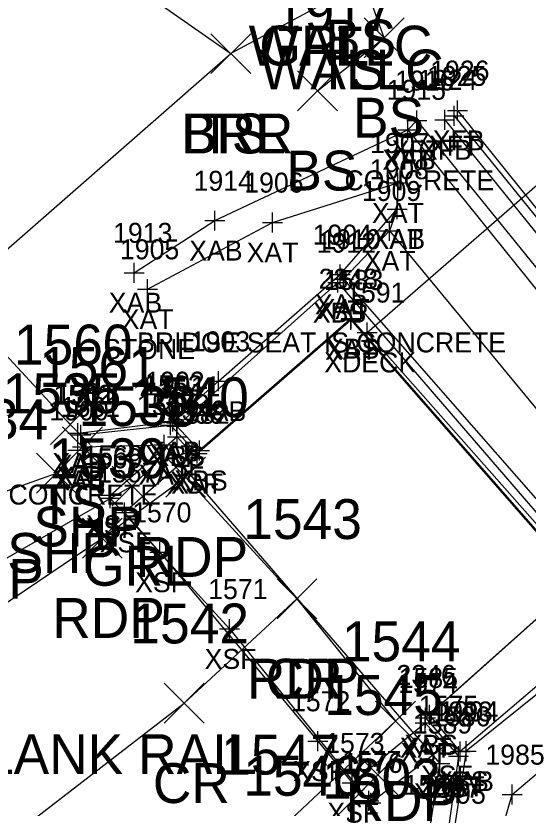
# Model space of a CAD drawing. Extents: x 1647133 to 1649138, y 411736 to 414924.
# Drawn here: x 1648828.16 to 1648853.85, y 412085.76 to 412125.47 of the extents above; entities that cross this region are included whole.
import ezdxf

# ---------------------------------------------------------------- set-up
doc = ezdxf.new("R2010")
doc.units = 0
for name, color, linetype in [('B_A', 7, 'Continuous'), ('B_C', 7, 'Continuous'), ('B_I', 7, 'Continuous'), ('B_TIC', 7, 'Continuous'), ('BDEFAULT', 7, 'Continuous'), ('BELB', 7, 'Continuous'), ('BFT', 7, 'Continuous'), ('BSE', 7, 'Continuous'), ('BSUBM', 7, 'Continuous'), ('L_A', 7, 'Continuous'), ('L_I', 7, 'Continuous'), ('L_TIC', 7, 'Continuous'), ('LABL', 7, 'Continuous'), ('LELB', 7, 'Continuous'), ('P_A', 7, 'Continuous'), ('P_I', 7, 'Continuous'), ('P_TIC', 7, 'Continuous'), ('PET', 7, 'Continuous'), ('PRC', 7, 'Continuous'), ('PSP', 7, 'Continuous'), ('R_A', 7, 'Continuous'), ('R_C', 7, 'Continuous'), ('R_I', 7, 'Continuous'), ('R_TIC', 7, 'Continuous'), ('RGR', 7, 'Continuous'), ('U_I', 7, 'Continuous')]:
    doc.layers.add(name, color=color, linetype=linetype)

msp = doc.modelspace()

# ---------------------------------------------------------------- linework, layer by layer
at = {"layer": 'B_TIC'}
for p, q in [((1648850.313, 412120.73), (1648850.388, 412120.73)), ((1648848.266, 412120.228), (1648848.341, 412120.228)), ((1648849.667, 412120.263), (1648849.743, 412120.263)), ((1648850.135, 412120.462), (1648850.211, 412120.462)), ((1648847.822, 412119.764), (1648847.898, 412119.764)), ((1648847.822, 412119.764), (1648847.898, 412119.764)), ((1648847.314, 412117.099), (1648847.39, 412117.099)), ((1648847.289, 412115.785), (1648847.364, 412115.785)), ((1648847.289, 412115.785), (1648847.364, 412115.785)), ((1648838.138, 412115.208), (1648838.214, 412115.208)), ((1648841.031, 412115.113), (1648841.106, 412115.113)), ((1648846.904, 412114.694), (1648846.979, 412114.694)), ((1648846.904, 412114.694), (1648846.979, 412114.694)), ((1648834.102, 412112.598), (1648834.177, 412112.598)), ((1648844.434, 412112.508), (1648844.51, 412112.508)), ((1648844.592, 412112.276), (1648844.668, 412112.276)), ((1648844.316, 412112.104), (1648844.391, 412112.104)), ((1648834.77, 412111.771), (1648834.846, 412111.771)), ((1648844.976, 412110.297), (1648845.052, 412110.297)), ((1648844.966, 412110.234), (1648845.042, 412110.234)), ((1648845.786, 412109.602), (1648845.861, 412109.602)), ((1648838.321, 412107.161), (1648838.396, 412107.161)), ((1648836.039, 412105.139), (1648836.115, 412105.139)), ((1648835.925, 412104.951), (1648836.001, 412104.951)), ((1648836.229, 412104.909), (1648836.304, 412104.909)), ((1648831.277, 412104.557), (1648831.353, 412104.557)), ((1648831.416, 412104.48), (1648831.492, 412104.48)), ((1648836.26, 412104.381), (1648836.336, 412104.381)), ((1648836.26, 412104.381), (1648836.336, 412104.381)), ((1648835.604, 412103.98), (1648835.68, 412103.98)), ((1648831.27, 412103.698), (1648831.346, 412103.698)), ((1648831.504, 412103.876), (1648831.58, 412103.876)), ((1648831.504, 412103.876), (1648831.58, 412103.876)), ((1648837.003, 412103.532), (1648837.078, 412103.532)), ((1648837.25, 412103.531), (1648837.325, 412103.531)), ((1648837.369, 412103.687), (1648837.445, 412103.687)), ((1648832.897, 412101.297), (1648832.973, 412101.297)), ((1648832.92, 412101.448), (1648832.996, 412101.448)), ((1648833.606, 412100.584), (1648833.682, 412100.584)), ((1648835.385, 412098.588), (1648835.461, 412098.588)), ((1648838.87, 412094.744), (1648838.946, 412094.744)), ((1648848.908, 412090.442), (1648848.984, 412090.442)), ((1648848.69, 412090.037), (1648848.765, 412090.037)), ((1648848.708, 412090.291), (1648848.784, 412090.291)), ((1648843.308, 412089.12), (1648843.384, 412089.12)), ((1648849.712, 412088.899), (1648849.787, 412088.899)), ((1648850.451, 412088.61), (1648850.527, 412088.61)), ((1648850.742, 412088.617), (1648850.818, 412088.617)), ((1648850.358, 412088.365), (1648850.433, 412088.365)), ((1648849.424, 412088.003), (1648849.499, 412088.003)), ((1648849.424, 412088.003), (1648849.499, 412088.003)), ((1648845.022, 412087.036), (1648845.097, 412087.036)), ((1648845.864, 412086.13), (1648845.939, 412086.13)), ((1648845.864, 412086.13), (1648845.939, 412086.13)), ((1648853.055, 412086.444), (1648853.131, 412086.444)), ((1648845.958, 412086.031), (1648846.034, 412086.031))]:
    msp.add_line(p, q, dxfattribs=at)
for points in [[(1648850.309, 412120.23), (1648850.309, 412121.23)], [(1648848.263, 412119.728), (1648848.263, 412120.728)], [(1648849.664, 412119.763), (1648849.664, 412120.763)], [(1648849.809, 412120.73), (1648850.809, 412120.73)], [(1648850.132, 412119.962), (1648850.132, 412120.962)], [(1648847.763, 412120.228), (1648848.763, 412120.228)], [(1648847.819, 412119.264), (1648847.819, 412120.264)], [(1648847.819, 412119.264), (1648847.819, 412120.264)], [(1648849.164, 412120.263), (1648850.164, 412120.263)], [(1648849.632, 412120.462), (1648850.632, 412120.462)], [(1648847.319, 412119.764), (1648848.319, 412119.764)], [(1648847.319, 412119.764), (1648848.319, 412119.764)], [(1648847.311, 412116.599), (1648847.311, 412117.599)], [(1648846.811, 412117.099), (1648847.811, 412117.099)], [(1648847.285, 412115.285), (1648847.285, 412116.285)], [(1648847.285, 412115.285), (1648847.285, 412116.285)], [(1648838.135, 412114.708), (1648838.135, 412115.708)], [(1648841.027, 412114.613), (1648841.027, 412115.613)], [(1648846.785, 412115.785), (1648847.785, 412115.785)], [(1648846.785, 412115.785), (1648847.785, 412115.785)], [(1648837.635, 412115.208), (1648838.635, 412115.208)], [(1648840.527, 412115.113), (1648841.527, 412115.113)], [(1648846.9, 412114.194), (1648846.9, 412115.194)], [(1648846.9, 412114.194), (1648846.9, 412115.194)], [(1648846.4, 412114.694), (1648847.4, 412114.694)], [(1648846.4, 412114.694), (1648847.4, 412114.694)], [(1648834.098, 412112.098), (1648834.098, 412113.098)], [(1648844.431, 412112.008), (1648844.431, 412113.008)], [(1648844.589, 412111.775), (1648844.589, 412112.776)], [(1648833.598, 412112.598), (1648834.598, 412112.598)], [(1648834.767, 412111.271), (1648834.767, 412112.271)], [(1648843.931, 412112.508), (1648844.931, 412112.508)], [(1648844.089, 412112.276), (1648845.089, 412112.276)], [(1648844.312, 412111.604), (1648844.312, 412112.604)], [(1648843.812, 412112.104), (1648844.812, 412112.104)], [(1648834.267, 412111.771), (1648835.267, 412111.771)], [(1648844.963, 412109.734), (1648844.963, 412110.734)], [(1648844.973, 412109.797), (1648844.973, 412110.797)], [(1648844.473, 412110.297), (1648845.473, 412110.297)], [(1648844.463, 412110.234), (1648845.463, 412110.234)], [(1648845.782, 412109.102), (1648845.782, 412110.102)], [(1648845.282, 412109.602), (1648846.282, 412109.602)], [(1648838.317, 412106.661), (1648838.317, 412107.661)], [(1648837.817, 412107.161), (1648838.817, 412107.161)], [(1648836.036, 412104.639), (1648836.036, 412105.639)], [(1648835.536, 412105.139), (1648836.536, 412105.139)], [(1648835.922, 412104.451), (1648835.922, 412105.451)], [(1648836.225, 412104.409), (1648836.225, 412105.409)], [(1648831.274, 412104.057), (1648831.274, 412105.057)], [(1648831.413, 412103.98), (1648831.413, 412104.98)], [(1648835.422, 412104.951), (1648836.422, 412104.951)], [(1648835.725, 412104.909), (1648836.725, 412104.909)], [(1648836.257, 412103.881), (1648836.257, 412104.881)], [(1648836.257, 412103.881), (1648836.257, 412104.881)], [(1648830.774, 412104.557), (1648831.774, 412104.557)], [(1648830.913, 412104.48), (1648831.913, 412104.48)], [(1648831.501, 412103.376), (1648831.501, 412104.376)], [(1648831.501, 412103.376), (1648831.501, 412104.376)], [(1648835.601, 412103.48), (1648835.601, 412104.48)], [(1648835.757, 412104.381), (1648836.757, 412104.381)], [(1648835.757, 412104.381), (1648836.757, 412104.381)], [(1648831.267, 412103.198), (1648831.267, 412104.198)], [(1648835.101, 412103.98), (1648836.101, 412103.98)], [(1648836.999, 412103.032), (1648836.999, 412104.032)], [(1648837.246, 412103.031), (1648837.246, 412104.031)], [(1648837.366, 412103.187), (1648837.366, 412104.187)], [(1648830.767, 412103.698), (1648831.767, 412103.698)], [(1648831.001, 412103.876), (1648832.001, 412103.876)], [(1648831.001, 412103.876), (1648832.001, 412103.876)], [(1648836.499, 412103.532), (1648837.499, 412103.532)], [(1648836.746, 412103.531), (1648837.746, 412103.531)], [(1648836.866, 412103.687), (1648837.866, 412103.687)], [(1648832.917, 412100.948), (1648832.917, 412101.948)], [(1648832.894, 412100.797), (1648832.894, 412101.797)], [(1648832.394, 412101.297), (1648833.394, 412101.297)], [(1648832.417, 412101.448), (1648833.417, 412101.448)], [(1648833.603, 412100.084), (1648833.603, 412101.084)], [(1648833.103, 412100.584), (1648834.103, 412100.584)], [(1648835.382, 412098.088), (1648835.382, 412099.088)], [(1648834.882, 412098.588), (1648835.882, 412098.588)], [(1648838.867, 412094.244), (1648838.867, 412095.244)], [(1648838.367, 412094.744), (1648839.367, 412094.744)], [(1648848.905, 412089.942), (1648848.905, 412090.942)], [(1648848.405, 412090.442), (1648849.405, 412090.442)], [(1648848.686, 412089.537), (1648848.686, 412090.537)], [(1648848.705, 412089.791), (1648848.705, 412090.791)], [(1648848.186, 412090.037), (1648849.186, 412090.037)], [(1648848.205, 412090.291), (1648849.205, 412090.291)], [(1648843.305, 412088.62), (1648843.305, 412089.62)], [(1648849.708, 412088.399), (1648849.708, 412089.399)], [(1648842.805, 412089.12), (1648843.805, 412089.12)], [(1648849.208, 412088.899), (1648850.208, 412088.899)], [(1648850.354, 412087.865), (1648850.354, 412088.865)], [(1648850.448, 412088.11), (1648850.448, 412089.11)], [(1648850.739, 412088.117), (1648850.739, 412089.117)], [(1648849.42, 412087.503), (1648849.42, 412088.503)], [(1648849.42, 412087.503), (1648849.42, 412088.503)], [(1648849.948, 412088.61), (1648850.948, 412088.61)], [(1648850.239, 412088.617), (1648851.239, 412088.617)], [(1648849.854, 412088.365), (1648850.854, 412088.365)], [(1648848.92, 412088.003), (1648849.92, 412088.003)], [(1648848.92, 412088.003), (1648849.92, 412088.003)], [(1648845.018, 412086.536), (1648845.018, 412087.536)], [(1648844.518, 412087.036), (1648845.518, 412087.036)], [(1648853.052, 412085.944), (1648853.052, 412086.944)], [(1648845.86, 412085.63), (1648845.86, 412086.63)], [(1648845.86, 412085.63), (1648845.86, 412086.63)], [(1648845.955, 412085.531), (1648845.955, 412086.531)], [(1648845.36, 412086.13), (1648846.36, 412086.13)], [(1648845.36, 412086.13), (1648846.36, 412086.13)], [(1648852.552, 412086.444), (1648853.552, 412086.444)], [(1648845.455, 412086.031), (1648846.455, 412086.031)]]:
    msp.add_lwpolyline(points, dxfattribs=at)
at = {"layer": 'BDEFAULT'}
for points in [[(1648836.257, 412104.381), (1648832.917, 412101.448), (1648832.894, 412101.297), (1648838.867, 412094.744), (1648845.86, 412086.13)], [(1648836.257, 412104.381), (1648836.999, 412103.532), (1648833.603, 412100.584), (1648835.382, 412098.588), (1648843.305, 412089.12), (1648845.018, 412087.036), (1648848.686, 412090.037), (1648849.708, 412088.899), (1648845.955, 412086.031), (1648845.86, 412086.13)]]:
    msp.add_lwpolyline(points, dxfattribs=at)
at = {"layer": 'BELB'}
msp.add_lwpolyline([(1648856.366, 412097.638), (1648845.782, 412109.602), (1648891.837, 412149.616), (1648923.124, 412177.419), (1648960.58, 412211.026), (1648974.892, 412224.907)], dxfattribs=at)
at = {"layer": 'BFT'}
for points in [[(1648850.309, 412120.73), (1648857.79, 412111.426), (1648863.239, 412104.817), (1648869.363, 412097.552)], [(1648847.819, 412119.764), (1648848.263, 412120.228), (1648867.344, 412096.727), (1648865.034, 412094.958)], [(1648849.664, 412120.263), (1648857.227, 412110.913), (1648862.559, 412104.443), (1648863.066, 412104.738)], [(1648850.132, 412120.462), (1648857.569, 412111.314), (1648863.066, 412104.738)]]:
    msp.add_lwpolyline(points, dxfattribs=at)
at = {"layer": 'BSE'}
for points in [[(1648836.225, 412104.909), (1648844.312, 412112.104), (1648858.599, 412095.552), (1648850.448, 412088.61), (1648848.905, 412090.442), (1648856.463, 412097.184), (1648844.973, 412110.297), (1648837.366, 412103.687)], [(1648837.366, 412103.687), (1648836.225, 412104.909)]]:
    msp.add_lwpolyline(points, dxfattribs=at)
at = {"layer": 'BSUBM'}
for points in [[(1648834.098, 412112.598), (1648838.135, 412115.208), (1648847.819, 412119.764), (1648865.962, 412097.201), (1648864.743, 412095.384), (1648859.561, 412089.524), (1648855.38, 412084.158), (1648852.149, 412076.311)], [(1648834.767, 412111.771), (1648841.027, 412115.113), (1648847.311, 412117.099), (1648847.285, 412115.785), (1648846.9, 412114.694), (1648844.589, 412112.276), (1648858.843, 412096.022)], [(1648831.267, 412103.698), (1648831.274, 412104.557), (1648836.036, 412105.139), (1648838.317, 412107.161), (1648844.431, 412112.508), (1648847.285, 412115.785)], [(1648846.9, 412114.694), (1648860.663, 412098.007), (1648858.843, 412096.022)], [(1648831.501, 412103.876), (1648831.413, 412104.48), (1648835.922, 412104.951), (1648837.246, 412103.531), (1648844.963, 412110.234), (1648856.402, 412097.156), (1648848.705, 412090.291), (1648850.354, 412088.365), (1648849.848, 412084.785), (1648848.957, 412084.934), (1648849.42, 412088.003)], [(1648831.501, 412103.876), (1648835.601, 412103.98), (1648849.42, 412088.003)], [(1648849.746, 412074.998), (1648853.052, 412086.444), (1648855.254, 412088.323), (1648859.087, 412092.575), (1648859.916, 412094.436), (1648858.907, 412095.188)], [(1648858.907, 412095.188), (1648850.739, 412088.617), (1648850.1, 412084.487)]]:
    msp.add_lwpolyline(points, dxfattribs=at)
at = {"layer": 'L_TIC'}
for points in [[(1648845.627, 412123.369), (1648847.627, 412125.369)], [(1648847.627, 412123.369), (1648845.627, 412125.369)], [(1648837.944, 412122.578), (1648839.944, 412124.578)], [(1648839.944, 412122.578), (1648837.944, 412124.578)], [(1648837.944, 412122.578), (1648839.944, 412124.578)], [(1648839.944, 412122.578), (1648837.944, 412124.578)], [(1648837.944, 412122.578), (1648839.944, 412124.578)], [(1648839.944, 412122.578), (1648837.944, 412124.578)], [(1648842.282, 412120.718), (1648844.282, 412122.718)], [(1648844.282, 412120.718), (1648842.282, 412122.718)], [(1648829.891, 412103.998), (1648831.891, 412105.998)], [(1648831.891, 412103.998), (1648829.891, 412105.998)]]:
    msp.add_lwpolyline(points, dxfattribs=at)
at = {"layer": 'LABL'}
for points in [[(1648799.847, 412141.142), (1648807.127, 412127.778), (1648818.199, 412115.65), (1648824.968, 412111.366), (1648838.944, 412123.578)], [(1648799.847, 412141.142), (1648813.37, 412139.189), (1648824.717, 412133.505), (1648838.944, 412123.578)]]:
    msp.add_lwpolyline(points, dxfattribs=at)
at = {"layer": 'LELB'}
for points in [[(1648843.282, 412121.718), (1648846.627, 412124.369), (1648845.222, 412128.283), (1648837.128, 412133.097)], [(1648844.864, 412126.782), (1648838.944, 412123.578)], [(1648824.968, 412111.366), (1648830.891, 412104.998)]]:
    msp.add_lwpolyline(points, dxfattribs=at)
at = {"layer": 'P_TIC'}
for points in [[(1648830.501, 412102.876), (1648832.501, 412104.876)], [(1648832.501, 412102.876), (1648830.501, 412104.876)], [(1648829.193, 412101.555), (1648831.193, 412103.555)], [(1648831.193, 412101.555), (1648829.193, 412103.555)], [(1648835.674, 412101.355), (1648837.674, 412103.355)], [(1648837.674, 412101.355), (1648835.674, 412103.355)], [(1648831.497, 412098.297), (1648833.497, 412100.297)], [(1648833.497, 412098.297), (1648831.497, 412100.297)], [(1648841.257, 412095.253), (1648843.257, 412097.253)], [(1648843.257, 412095.253), (1648841.257, 412097.253)], [(1648841.257, 412095.253), (1648843.257, 412097.253)], [(1648843.257, 412095.253), (1648841.257, 412097.253)], [(1648835.598, 412090.021), (1648837.598, 412092.021)], [(1648837.598, 412090.021), (1648835.598, 412092.021)], [(1648846.201, 412089.123), (1648848.201, 412091.123)], [(1648848.201, 412089.123), (1648846.201, 412091.123)]]:
    msp.add_lwpolyline(points, dxfattribs=at)
at = {"layer": 'PET'}
msp.add_lwpolyline([(1648804.077, 412081.379), (1648817.165, 412089.126), (1648824.651, 412094.018), (1648832.497, 412099.297), (1648836.674, 412102.355), (1648842.257, 412096.253), (1648847.201, 412090.123), (1648841.152, 412084.448), (1648829.009, 412072.706), (1648818.716, 412064.019)], dxfattribs=at)
at = {"layer": 'PRC'}
msp.add_lwpolyline([(1648812.617, 412072.528), (1648836.598, 412091.021), (1648842.257, 412096.253)], dxfattribs=at)
at = {"layer": 'PSP'}
msp.add_lwpolyline([(1648817.165, 412089.126), (1648822.814, 412097.685), (1648826.528, 412101.257), (1648830.193, 412102.555), (1648831.501, 412103.876)], dxfattribs=at)
at = {"layer": 'R_TIC'}
for points in [[(1648832.997, 412100.912), (1648834.997, 412102.912)], [(1648834.997, 412100.912), (1648832.997, 412102.912)], [(1648845.316, 412086.432), (1648847.316, 412088.432)], [(1648847.316, 412086.432), (1648845.316, 412088.432)]]:
    msp.add_lwpolyline(points, dxfattribs=at)
at = {"layer": 'RGR'}
for points in [[(1648824.517, 412096.47), (1648833.997, 412101.912)], [(1648846.316, 412087.432), (1648842.313, 412083.387), (1648831.517, 412072.268)]]:
    msp.add_lwpolyline(points, dxfattribs=at)

# ---------------------------------------------------------------- texts
at = {"layer": 'B_A'}
for s, p in [('XFT', (1648848.876, 412118.462)), ('XFB', (1648849.069, 412118.73)), ('XFT', (1648847.007, 412118.228)), ('XFB', (1648848.424, 412118.263)), ('XAB', (1648846.539, 412117.764)), ('XFT', (1648846.563, 412117.764)), ('XAT', (1648846.016, 412115.099)), ('XAT', (1648845.99, 412113.785)), ('XAB', (1648846.006, 412113.785)), ('XAB', (1648836.855, 412113.208)), ('XAT', (1648839.732, 412113.113)), ('XAT', (1648845.605, 412112.694)), ('XAT', (1648845.605, 412112.694)), ('XAB', (1648832.819, 412110.598)), ('XAB', (1648843.151, 412110.508)), ('XBS', (1648843.052, 412110.104)), ('XAT', (1648843.294, 412110.276)), ('XAT', (1648833.472, 412109.771)), ('XAT', (1648843.668, 412108.234)), ('XBS', (1648843.713, 412108.297)), ('XDECK', (1648843.625, 412107.602)), ('XAB', (1648837.038, 412105.161)), ('XAT', (1648834.627, 412102.951)), ('XAB', (1648834.756, 412103.139)), ('XBS', (1648834.966, 412102.909)), ('XAB', (1648829.994, 412102.557)), ('XAT', (1648830.118, 412102.48)), ('XSF', (1648835.016, 412102.381)), ('XSF', (1648835.016, 412102.381)), ('XAT', (1648830.206, 412101.876)), ('XAT', (1648830.206, 412101.876)), ('XAT', (1648834.306, 412101.98)), ('XAB', (1648829.987, 412101.698)), ('XSF', (1648835.759, 412101.532)), ('XAT', (1648835.951, 412101.531)), ('XBS', (1648836.106, 412101.687)), ('XSF', (1648831.676, 412099.448)), ('XSF', (1648831.654, 412099.297)), ('XSF', (1648832.362, 412098.584)), ('XSF', (1648834.141, 412096.588)), ('XSF', (1648837.627, 412092.744)), ('XAT', (1648847.41, 412088.291)), ('XBS', (1648847.645, 412088.442)), ('XSF', (1648847.446, 412088.037)), ('XSF', (1648842.065, 412087.12)), ('XSF', (1648848.468, 412086.899)), ('XAT', (1648849.059, 412086.365)), ('XBS', (1648849.188, 412086.61)), ('XAB', (1648849.459, 412086.617)), ('XAT', (1648848.125, 412086.003)), ('XAT', (1648848.125, 412086.003)), ('XSF', (1648843.778, 412085.036))]:
    msp.add_text(s, height=1, dxfattribs=at).set_placement(p)
at = {"layer": 'B_C'}
for s, p in [('CONCRETE', (1648844.64, 412116.728)), ('BRIDGE SEAT IS CONCRETE', (1648834.241, 412108.604)), ('STONE', (1648832.539, 412108.271)), ('CONCRETE', (1648827.791, 412100.98))]:
    msp.add_text(s, height=1, dxfattribs=at).set_placement(p)
at = {"layer": 'B_I'}
for s, p in [('1926', (1648848.935, 412122.23)), ('1916', (1648847.172, 412121.728)), ('1924', (1648848.317, 412121.763)), ('1925', (1648848.785, 412121.962)), ('1915', (1648846.756, 412121.264)), ('1915', (1648846.756, 412121.264)), ('1907', (1648845.925, 412118.599)), ('1908', (1648845.9, 412117.285)), ('1908', (1648845.9, 412117.285)), ('1914', (1648837.072, 412116.708)), ('1906', (1648839.614, 412116.613)), ('1909', (1648845.51, 412116.194)), ('1909', (1648845.51, 412116.194)), ('1913', (1648833.035, 412114.098)), ('1904', (1648843.045, 412114.008)), ('1910', (1648843.483, 412113.776)), ('1905', (1648833.381, 412113.271)), ('1912', (1648843.249, 412113.604)), ('2348', (1648843.343, 412111.797)), ('1583', (1648843.616, 412111.734)), ('1591', (1648844.719, 412111.102)), ('1903', (1648836.931, 412108.661)), ('1902', (1648834.65, 412106.639)), ('1563', (1648834.552, 412106.451)), ('1911', (1648835.446, 412106.409)), ('1562', (1648830.043, 412105.98)), ('1901', (1648830.171, 412106.057)), ('1565', (1648834.886, 412105.881)), ('1565', (1648834.886, 412105.881)), ('1561', (1648830.414, 412105.376)), ('1561', (1648830.414, 412105.376)), ('1564', (1648834.231, 412105.48)), ('1900', (1648829.838, 412105.198)), ('1566', (1648835.602, 412105.032)), ('2349', (1648835.732, 412105.187)), ('1582', (1648835.9, 412105.031)), ('1568', (1648831.546, 412102.948)), ('1569', (1648831.52, 412102.797)), ('1567', (1648832.233, 412102.084)), ('1570', (1648833.992, 412100.088)), ('1571', (1648837.804, 412096.244)), ('2346', (1648847.247, 412091.942)), ('1585', (1648847.358, 412091.791)), ('1574', (1648847.34, 412091.537)), ('1572', (1648841.958, 412090.62)), ('1575', (1648848.362, 412090.399)), ('1586', (1648848.98, 412089.865)), ('1993', (1648849.102, 412090.11)), ('1994', (1648849.392, 412090.117)), ('1589', (1648848.07, 412089.503)), ('1589', (1648848.07, 412089.503)), ('1573', (1648843.672, 412088.536)), ('1985', (1648851.705, 412087.944)), ('1577', (1648844.514, 412087.63)), ('1577', (1648844.514, 412087.63)), ('1576', (1648844.581, 412087.531)), ('1588', (1648847.61, 412086.434)), ('1587', (1648848.501, 412086.285)), ('1995', (1648848.753, 412085.987))]:
    msp.add_text(s, height=1, dxfattribs=at).set_placement(p)
at = {"layer": 'L_A'}
for s, p in [('WALLC', (1648839.836, 412122.977)), ('BS', (1648843.663, 412123.283)), ('WALLC', (1648840.4, 412121.782)), ('WALLC', (1648840.4, 412121.782)), ('TS', (1648843.274, 412121.782)), ('BS', (1648845.068, 412119.369)), ('TS', (1648837.353, 412118.578)), ('BRR', (1648836.432, 412118.578)), ('BRL', (1648836.487, 412118.578)), ('BS', (1648841.723, 412116.718)), ('TS', (1648829.3, 412099.998))]:
    msp.add_text(s, height=2, dxfattribs=at).set_placement(p)
at = {"layer": 'L_I'}
for s, p in [('1917', (1648841.156, 412124.718)), ('1560', (1648828.064, 412107.998))]:
    msp.add_text(s, height=2, dxfattribs=at).set_placement(p)
at = {"layer": 'P_A'}
for s, p in [('SHP', (1648829.036, 412098.876)), ('SHP', (1648827.728, 412097.555)), ('RDP', (1648834.162, 412097.355)), ('SHP', (1648824.064, 412096.257)), ('RDP', (1648829.985, 412094.297)), ('RDP', (1648839.746, 412091.253)), ('CR', (1648840.69, 412091.253)), ('CR', (1648835.031, 412086.021)), ('RDP', (1648844.689, 412085.123))]:
    msp.add_text(s, height=2, dxfattribs=at).set_placement(p)
at = {"layer": 'P_I'}
for s, p in [('1561', (1648829.328, 412106.876)), ('1535', (1648827.5, 412105.555)), ('1540', (1648833.894, 412105.355)), ('1534', (1648823.835, 412104.257)), ('1539', (1648829.796, 412102.297)), ('1543', (1648839.564, 412099.253)), ('1543', (1648839.564, 412099.253)), ('1542', (1648833.905, 412094.021)), ('1544', (1648844.508, 412093.123)), ('1547', (1648838.459, 412087.448))]:
    msp.add_text(s, height=2, dxfattribs=at).set_placement(p)
at = {"layer": 'R_A'}
for p in [(1648840.37, 412122.982), (1648831.54, 412096.912)]:
    msp.add_text('GRL', height=2, dxfattribs=at).set_placement(p)
at = {"layer": 'R_C'}
msp.add_text('WOOD POST W/ PLANK RAIL', height=2, dxfattribs=at).set_placement((1648803.383, 412087.47))
at = {"layer": 'R_I'}
for s, p in [('1538', (1648831.304, 412104.912)), ('1545', (1648843.623, 412090.432)), ('1546', (1648839.565, 412086.387))]:
    msp.add_text(s, height=2, dxfattribs=at).set_placement(p)
at = {"layer": 'U_I'}
msp.add_text('1603', height=2, dxfattribs=at).set_placement((1648843.528, 412086.243))

doc.saveas('drawing.dxf')
